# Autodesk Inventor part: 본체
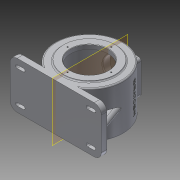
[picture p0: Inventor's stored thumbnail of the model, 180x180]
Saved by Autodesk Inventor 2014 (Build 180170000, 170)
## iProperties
Created: 2015-06
Part Number: 본체
Material: Aluminum 6061
Document SubType Name: Modeling
Designer: user
Density: 2.71 g/cm^3
Appearance: Aluminum - Flat
Mass: 3274.55 g
Surface Area: 2341.75 cm^2
Volume: 1208.32 cm^3
Author: user
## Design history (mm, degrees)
sketch "Sketch2"
  geometry: C1 r 85 at (0, 0); 1 further point
  constraints: 1 centre point, 1 coincident
extrude "Extrusion2" new body sketch "Sketch2" distance "d6" = 118; taper "d7" = 0 deg
workplane "Work Plane1"
sketch "Sketch3"
  geometry: L1 (115, 118)-(-115, 118); L2 (-115, 118)-(-115, 0); L3 (-115, 0)-(115, 0); L4 (115, 0)-(115, 118); 2 further points
  constraints: 8 end point, 1 coincident, 1 midpoint
  dimensions: "d9" = 230 distance of L2.end L3.end; "d10" = 118 distance of L1.end L2.end; "d11" = 115 distance from line of point (0, 0) L4
extrude "Extrusion3" join sketch "Sketch3" distance "d12" = 14; taper "d13" = 0 deg
workplane "Work Plane2"
sketch "Sketch4"
  geometry: L1 (-42.5, 101.5)-(42.5, 101.5); L2 (42.5, 101.5)-(42.5, 16.5); L3 (42.5, 16.5)-(-42.5, 16.5); L4 (-42.5, 16.5)-(-42.5, 101.5); L5 (-42.5, 101.5)-(42.5, 16.5); L6 (42.5, 101.5)-(-42.5, 16.5); L7 (85, 118)-(-85, 118) reference; L8 (-115, 118)-(-115, 0) reference; 4 further points
  constraints: 12 end point, 2 horizontal, 2 midpoint, 2 vertical
  dimensions: "d15" = 85 distance of L1.end L2.end; "d16" = 85 distance of L2.end L3.end; "d17" = 59 distance from line of point (0, 59) L7; "d18" = 115 distance from line of point (0, 59) L8
extrude "Extrusion4" join sketch "Sketch4" stored distance "d19" = 14; taper "d20" = 0 deg
sketch "Sketch5"
  geometry: C1 r 65 at (0, 0); A1 r 85 centre (0, 0) between (46.733, -71) and (-46.733, -71) reference
  constraints: 1 centre point, 1 coincident
extrude "Extrusion5" join sketch "Sketch5" distance "d21" = 13; taper "d22" = 0 deg
sketch "Sketch6"
  geometry: L1 (0, 11.5)-(29.368, 11.5); L2 (29.368, 11.5)-(31, 8); L3 (31, 8)-(77, 8); L4 (77, 8)-(77, 110); L5 (77, 110)-(0, 110); L6 (0, 110)-(0, 11.5); L7 (-71, 0)-(85, 0) reference; L8 (85, 118)-(-71, 118) reference; L9 (22.388, 11.5)-(0, 11.5); 1 further point
  constraints: 14 end point, 2 point on line
  dimensions: "d23" = 115 deg angle of L2 L3; "d24" = 102 distance of L3.end L4.end; "d25" = 77 distance between parallel lines of L6 L4; "d26" = 31 horizontal distance of point (0, 0) L2.end; "d27" = 8 distance between parallel lines of L3 L7; "d28" = 8 distance between parallel lines of L8 L5; "d29" = 3.5 distance between parallel lines of L1 L3
revolve "Revolution1" sketch "Sketch6" stored, may be unused: angle "d30" = 90 deg
sketch "Sketch7"
  geometry: C1 r 65 at (0, 0); A1 r 85 centre (0, 0) between (46.733, -71) and (-46.733, -71) reference
  constraints: 1 centre point, 1 coincident
extrude "Extrusion6" join sketch "Sketch7" taper "d22" = 0 deg; distance "d31" = 3; taper "d32" = 0 deg
sketch "Sketch8"
  geometry: C1 r 65 at (0, 0) reference; C2 r 47.5 at (0, 0)
  constraints: 1 centre point, 1 coincident
extrude "Extrusion7" cut sketch "Sketch8" distance "d33" = 44.25; taper "d34" = 0 deg
sketch "Sketch9"
  geometry: C1 r 29.368 at (0, 0) reference; C2 r 23.5 at (0, 0)
  constraints: 1 centre point, 1 coincident
  dimensions: "d39" = 47 diameter of C2
extrude "Extrusion8" cut sketch "Sketch9" distance "d40" = 14; taper "d41" = 0 deg
sketch "Sketch10"
  geometry: C1 r 23.5 at (0, 0) reference; C2 r 15 at (0, 0)
  constraints: 1 centre point, 1 coincident
extrude "Extrusion9" cut sketch "Sketch10" distance "d42" = 3; taper "d43" = 0 deg
sketch "Sketch11"
  geometry: C1 r 35 at (0, -59); 1 further point
  constraints: 1 centre point
extrude "Extrusion10" cut sketch "Sketch11" distance "d44" = 58.25; taper "d45" = 0 deg
sketch "Sketch12"
  geometry: L1 (-35.5, -23.5)-(35.5, -23.5); L2 (35.5, -23.5)-(35.5, -94.5); L3 (35.5, -94.5)-(-35.5, -94.5); L4 (-35.5, -94.5)-(-35.5, -23.5); C1 r 35 at (0, -59) reference; 5 further points
  constraints: 8 end point, 4 coincident, 2 horizontal, 2 vertical
  dimensions: "d46" = 71 distance of L1.start L1.end; "d47" = 71 distance of L1.end L2.end; "d48" = 35.5 distance from line of C1.centre L1; "d49" = 35.5 distance from line of L2 C1.centre
hole "Hole1" sketch "Sketch12" at (-35.5, -23.5), (-35.5, -94.5), (35.5, -94.5), (35.5, -23.5) diameter "d50" = 3.242; stored, may be unused: countersink angle "d54" = 90 deg, drill point angle "d56" = 118 deg; dims "d51" = 10, "d52" = 47, "d53" = 14, "d55" = 13
workplane "Work Plane3"
sketch "Sketch13"
  geometry: L1 (-84.87, -4.703)-(-109, -71); L2 (-115, -85)-(-115, -71) reference; L3 (-46.733, -71)-(-115, -71) reference; L4 (84.87, -4.703)-(109, -71); L5 (115, -85)-(115, -71) reference; L6 (115, -71)-(46.733, -71) reference; A1 r 85 centre (0, 0) between (46.733, -71) and (-46.733, -71) reference; 1 further point
  constraints: 4 end point, 2 point on circle, 2 point on line
  dimensions: "d60" = 6 distance of L1.end L2.end; "d61" = 110 deg angle of L1 L3; "d62" = 6 distance from line of L5 L4.end; "d63" = 110 deg angle of L6 L4
feature "Rib1" sketch "Sketch13" dims "d64" = 1, "d65" = 15, "d66" = 0, "d67" = 0, "d68" = 1, "d69" = 1
mirror "Mirror1"
sketch "Sketch14"
  geometry: L1 (62.267, 0)-(0, 0) reference; L2 (0, 0)-(24.13, 66.297) reference; A1 r 85 centre (109, 71) between (24.13, 66.297) and (62.267, 0) reference
sketch "Sketch15"
  geometry: L1 (115, -118)-(115, 0) reference; L2 (81, -27)-(97, -27); L3 (97, -9)-(81, -9); L4 (-115, 0)-(-115, -118) reference; L5 (-115, -59)-(115, -59); A1 r 9 centre (81, -18) between (81, -9) and (81, -27); A2 r 9 centre (97, -18) between (97, -27) and (97, -9); 1 further point
  constraints: 6 end point, 4 point on circle, 2 centre point, 2 horizontal, 2 midpoint
  dimensions: "d70" = 18 diameter of A2; "d71" = 18 diameter of A1; "d72" = 16 distance of A2.centre A1.centre; "d73" = 97 horizontal distance of A2.centre point (0, 0); "d74" = 82 diameter of A2.centre L5; "d75" = 82 diameter of A1.centre L5
extrude "Extrusion11" join sketch "Sketch15" distance "d76" = 3; taper "d77" = 0 deg
sketch "Sketch16"
  geometry: L1 (81, -27)-(97, -27) reference; L2 (97, -9)-(81, -9) reference; L3 (81, -22)-(97, -22); L4 (97, -14)-(81, -14); A1 r 9 centre (81, -18) between (81, -9) and (81, -27) reference; A2 r 9 centre (97, -18) between (97, -27) and (97, -9) reference; A3 r 4 centre (81, -18) between (81, -14) and (81, -22); A4 r 4 centre (97, -18) between (97, -22) and (97, -14); 1 further point
  constraints: 4 end point, 4 point on circle, 2 centre point, 3 other
  dimensions: "d78" = 5 distance between parallel lines of L4 L2
extrude "Extrusion12" cut sketch "Sketch16" stored distance "d79" = 3; taper "d80" = 0 deg
mirror "Mirror2"
mirror "Mirror3"
workplane "Work Plane4"
workplane "Work Plane5"
sketch "Sketch17"
  geometry: L1 (-84.098, 0)-(85, 0) reference; 3 further points
  constraints: 1 other
  dimensions: "d82" = 59 distance from line of L1 point (0.451, 59)
emboss "Emboss1" sketch "Sketch17" dims "d15" = 85, "d16" = 85, "d17" = 59, "d18" = 115, "d84" = 0.5, "d85" = 0
fillet "Fillet1" dims "d86" = 7
fillet "Fillet2" dims "d87" = 3
fillet "Fillet3" dims "d88" = 18
fillet "Fillet4" dims "d89" = 3
fillet "Fillet5" dims "d90" = 3
chamfer "Chamfer1" distance "d91" = 1; stored, may be unused: second distance "d92" = 2, angle "d93" = 45 deg
fillet "Fillet6" dims "d94" = 0.3
sketch "Sketch19"
  geometry: C1 r 48.5 at (0, 0) reference; A1 r 55 centre (0, 0) between (0, 55) and (55, 0); 2 further points
  constraints: 4 point on circle, 1 centre point, 1 coincident
hole "Hole2" sketch "Sketch19" at (-55, 0), (0, 55), (55, 0), (0, -55) diameter "d95" = 3.242; stored, may be unused: countersink angle "d99" = 90 deg, drill point angle "d101" = 118 deg; dims "d96" = 3, "d97" = 4, "d98" = 2, "d100" = 27.25
fillet "Fillet7" dims "d102" = 9
body "Solid2"
other parameters: "d8" = -85, "d14" = 173, "d81" = 65 deg
